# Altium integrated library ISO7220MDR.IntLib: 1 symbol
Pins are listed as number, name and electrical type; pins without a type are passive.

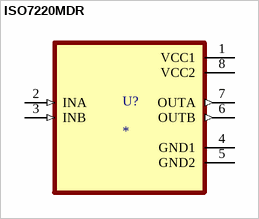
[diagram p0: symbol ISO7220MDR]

## ISO7220MDR
designator U?
Dual-channel, 2/0, 150-Mbps digital isolator 8-SOIC -40 to 125; MP: ISO7220MDR; MF: Texas Instruments
footprint SOIC127P599X175-8N
pins: 1 VCC1 (power), 2 INA (in), 3 INB (in), 4 GND1 (power), 5 GND2 (power), 6 OUTB (out), 7 OUTA (out), 8 VCC2 (power)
